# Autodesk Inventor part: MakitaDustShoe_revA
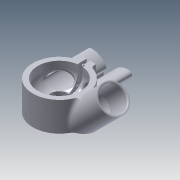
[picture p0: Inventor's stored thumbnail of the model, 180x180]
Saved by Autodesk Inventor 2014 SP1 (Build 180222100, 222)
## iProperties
Created: 2014-02
Part Number: MakitaDustShoe_revA
Material: ABS Plastic
Document SubType Name: Modeling
Designer: RagnarMac
Density: 1.06 g/cm^3
Appearance: PTFE
Author: RagnarMac
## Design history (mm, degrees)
sketch "Sketch2"
  geometry: L1 (-3.267, 9.572)-(-3.267, -36.428); L2 (-35.767, 16.355)-(-35.767, 6.355); L3 (-35.767, 16.355)-(-39.767, 16.355); L4 (-39.767, 16.355)-(-39.767, 4.355); L5 (-16.767, -13.645)-(-16.767, -17.645); L6 (-16.767, -13.645)-(-16.767, -9.969); L7 (-16.767, -9.969)-(-19.408, -13.645); L8 (-16.767, -17.645)-(-16.767, -27.645); L9 (-16.767, -27.645)-(-20.767, -27.645); L10 (-20.767, -27.645)-(-20.767, -17.094); A1 r 24.445 centre (-15.441, 6.764) between (-39.767, 4.355) and (-20.767, -17.094); A2 r 20.405 centre (-15.362, 6.355) between (-35.767, 6.355) and (-19.408, -13.645); 1 further point
  constraints: 20 end point, 4 point on circle, 3 parallel, 3 perpendicular, 2 centre point, 1 collinear, 1 point on line, 1 tangent, 1 vertical
  dimensions: "d0" = 46 distance of L1.start L1.end; "d1" = 10 distance of L2.start L2.end; "d2" = 32.5 distance between parallel lines of L1 L2; "d4" = 4 distance of L2.start L3.end; "d5" = 4 distance of L5.start L5.end; "d27" = 13.5 distance between parallel lines of L1 L5; "d42" = 20 vertical distance of L2.end L5.start; "d43" = 12 distance of L3.end L4.end; "d96" = 10 distance of L5.end L8.end; "d97" = 4 distance of L8.end L9.end
revolve "Revolution1" sketch "Sketch2" stored, may be unused: angle "d6" = 90 deg
sketch "Sketch11"
  geometry: L1 (-5.065, 36.147)-(-5.065, 46.147); L2 (-5.065, 46.147)-(-9.065, 46.147); L3 (-9.065, 46.147)-(-9.065, 35.356); L4 (-9.065, 35.356)-(-5.065, 36.147); L5 (0, 68.018)-(0, 7.693); L6 (9.065, 35.356)-(5.065, 36.147); L7 (9.065, 46.147)-(9.065, 35.356); L8 (5.065, 46.147)-(9.065, 46.147); L9 (5.065, 36.147)-(5.065, 46.147); A1 r 36.5 centre (0, 0) between (-5.065, 36.147) and (-9.065, 35.356) reference; 1 further point
  constraints: 18 end point, 4 symmetric about line, 2 perpendicular, 2 point on circle, 1 parallel, 1 vertical
  dimensions: "d28" = 10 distance of L1.start L1.end; "d29" = 4 distance of L1.end L2.end
extrude "Extrusion9" join sketch "Sketch11" distance "d30" = 10; taper "d31" = 0 deg
sketch "Sketch12"
  geometry: C1 r 1.6 at (5, 5.395); 1 further point
  constraints: 1 centre point
  dimensions: "d32" = 3.2 diameter of C1
extrude "Extrusion10" cut sketch "Sketch12" stored distance "d33" = 10; taper "d34" = 0 deg
sketch "Sketch13"
  geometry: L1 (0, 10.79)-(0, 0) reference; L2 (0, 10.79)-(-10, 10.79) reference; L3 (-10, 0)-(-10, 10.79) reference; L4 (0, 0)-(-10, 0) reference; L5 (-2.1, 3.721)-(-5, 2.047); L6 (-5, 2.047)-(-7.9, 3.721); L7 (-7.9, 3.721)-(-7.9, 7.07); L8 (-7.9, 7.07)-(-5, 8.744); L9 (-5, 8.744)-(-2.1, 7.07); L10 (-2.1, 7.07)-(-2.1, 3.721); C1 r 1.6 at (-5, 5.395) reference; 2 further points
  constraints: 12 end point, 1 coincident, 1 parallel, 13 other
  dimensions: "d35" = 5.8 distance between parallel lines of L10 L7
extrude "Extrusion11" join sketch "Sketch13" distance "d36" = 4; taper "d37" = 0 deg
sketch "Sketch15"
  geometry: L1 (-18.13, -10.79)-(-18.13, 0) reference; L2 (0, 0)-(0, -10) reference; L3 (-18.13, -8.649)-(-18.13, -14.52); L4 (-18.13, -14.52)-(-11.476, -10); L5 (-11.476, -10)-(-18.13, -8.649); 1 further point
  constraints: 6 end point, 1 parallel, 1 point on line
extrude "Extrusion12" join sketch "Sketch15" stored distance "d38" = 4; taper "d39" = 0 deg
sketch "Sketch16"
  geometry: L1 (0, 0)-(0, -10) reference; L2 (-10.13, -10)-(-5.065, -46.147); L3 (-5.065, -46.147)-(0, -10); L4 (0, -10)-(0, 0); L5 (-10.13, 0)-(0, 0); L6 (-10.13, 0)-(-10.13, -10); A1 r 36.5 centre (-5.065, -46.147) between (0, -10) and (-10.13, -10) reference; 1 further point
  constraints: 10 end point, 2 perpendicular, 1 collinear
extrude "Extrusion13" cut sketch "Sketch16" distance "d40" = 50; taper "d41" = 0 deg
fillet "Fillet5" dims "d59" = 5
fillet "Fillet6" dims "d60" = 2
sketch "Sketch17"
  geometry: L1 (-8, 0)-(-8, 10) reference; L2 (5.065, 40.511)-(5.065, -19.74); A1 r 24.445 centre (-7.109, 9.591) between (-12.435, 33.449) and (-31.435, 12) reference; 8 further points; 4 other entities
  constraints: 5 symmetric about line, 2 coincident, 2 end point, 2 vertical, 1 parallel, 8 other
extrude "Extrusion18" join sketch "Sketch17" stored distance "d62" = 10; taper "d63" = 0 deg
extrude "Extrusion19" cut sketch "Sketch17" stored distance "d64" = 33; taper "d65" = 0 deg
fillet "Fillet9" dims "d67" = 5
workplane "Work Plane4"
sketch "Sketch21"
  geometry: C1 r 17.5 at (22.26, -46.147); C2 r 20.5 at (22.26, -46.147); 4 further points; 1 other entity
  constraints: 2 centre point, 1 coincident, 1 other
  dimensions: "d76" = 35 diameter of C1; "d77" = 41 diameter of C2
extrude "Extrusion22" join sketch "Sketch21" distance "d78" = 42; taper "d79" = 0 deg
sketch "Sketch22"
  geometry: C1 r 39.904 at (13.065, -46.147); C2 r 36.5 at (13.065, -46.147); A1 r 36.5 centre (13.065, -46.147) between (-2.823, -13.286) and (23.555, -11.187) reference; A2 r 32.5 centre (13.065, -46.147) between (8.555, -13.961) and (17.575, -13.961) reference; 1 further point
  constraints: 2 centre point, 2 coincident, 1 concentric
extrude "Extrusion23" join sketch "Sketch22" distance "d80" = 44; taper "d81" = 0 deg
extrude "Extrusion24" join sketch "Sketch21" stored distance "d82" = 34; taper "d83" = 0 deg
sketch "Sketch23"
  geometry: C1 r 12.5 at (22.151, -45.865); C2 r 18 at (22.151, -45.865); 1 further point
  constraints: 2 centre point, 1 coincident
  dimensions: "d84" = 25 diameter of C1; "d85" = 36 diameter of C2
extrude "Extrusion25" join sketch "Sketch23" stored distance "d86" = 34; taper "d87" = 0 deg
extrude "Extrusion26" cut sketch "Sketch23" stored distance "d88" = 34; taper "d89" = 0 deg
fillet "Fillet10" dims "d90" = 2
fillet "Fillet11" dims "d91" = 2
fillet "Fillet12" dims "d92" = 20
chamfer "Chamfer1" distance "d93" = 5; stored, may be unused: second distance "d94" = 2, angle "d95" = 45 deg
extrude "Extrusion27" cut sketch "Sketch16" stored distance "d98" = 34; taper "d99" = 0 deg
extrude "Extrusion28" cut sketch "Sketch17" distance "d100" = 34; taper "d101" = 0 deg
sketch "Sketch24"
  geometry: L1 (0, 0)-(0, 38.982); L2 (-12.901, 11.824)-(-22.733, 28.557); L3 (-17.817, 31.856)-(-8.187, 15.467); L4 (-22.733, 28.557)-(-22.733, 31.856); L5 (-22.733, 31.856)-(-17.817, 31.856); L6 (-8.187, 15.467)-(-8.187, 11.824); L7 (-8.187, 11.824)-(-12.901, 11.824); L8 (8.187, 11.824)-(12.901, 11.824); L9 (8.187, 15.467)-(8.187, 11.824); L10 (22.733, 31.856)-(17.817, 31.856); L11 (22.733, 28.557)-(22.733, 31.856); L12 (17.817, 31.856)-(8.187, 15.467); L13 (12.901, 11.824)-(22.733, 28.557); A1 r 17.5 centre (0, 0) between (-2.428, 17.331) and (2.428, 17.331) reference; A2 r 36.5 centre (0, 0) between (-5.065, 36.147) and (-30.633, 19.846) reference; 1 further point
  constraints: 26 end point, 6 symmetric about line, 4 point on circle, 3 perpendicular, 2 parallel, 1 vertical
extrude "Extrusion29" join sketch "Sketch24" stored distance "d102" = 20; taper "d103" = 0 deg
sketch "Sketch25"
  geometry: L1 (40.316, 44)-(-34.839, 44) reference; L2 (-48.22, 77.777)-(72.822, 77.777); L3 (72.822, 77.777)-(72.822, 44); L4 (72.822, 44)-(-48.22, 44); L5 (-48.22, 44)-(-48.22, 77.777); 2 further points
  constraints: 8 end point, 2 parallel, 1 horizontal, 1 perpendicular
extrude "Extrusion30" cut sketch "Sketch25" distance "d104" = 120; taper "d105" = 0 deg
fillet "Fillet13" dims "d106" = 5
sketch "Sketch27"
  geometry: L1 (44, 19)-(34, 19) reference; L2 (44, 23)-(44, 19) reference; L3 (44, 23)-(32, 23) reference; L4 (0, 4)-(10.551, 4) reference; L5 (0, 0)-(0, 4) reference; L6 (17.676, 0)-(0, 0) reference; L7 (14, 2.641)-(17.676, 0) reference; A1 r 20.405 centre (34, -1.405) between (34, 19) and (24.312, 16.553) reference; A2 r 24.445 centre (34.409, -1.326) between (32, 23) and (10.551, 4) reference; A3 r 20.405 centre (34, -1.405) between (18.81, 12.22) and (14, 2.641) reference; 1 further point
  constraints: 1 other
extrude "Extrusion31" join sketch "Sketch27" distance "d107" = 2; taper "d108" = 0 deg
sketch "Sketch28"
  geometry: L1 (10, 0)-(10, -10) reference; L2 (10, 0)-(0, 0) reference; L3 (0, -6.566)-(0, 0) reference; L4 (-34, -6.566)-(0, -6.566) reference; L5 (-34, -10)-(-34, -6.566) reference; L6 (-2, -10)-(-34, -10) reference; L7 (10, -10)-(-2, -10) reference; L8 (3.909, -6.566)-(6.091, -6.566) reference; A1 r 1.6 centre (5, -5.395) between (6.091, -6.566) and (3.909, -6.566) reference; 2 further points
extrude "Extrusion32" join sketch "Sketch28" distance "d109" = 5; taper "d110" = 0 deg
sketch "Sketch29"
  geometry: C1 r 1.6 at (5, -5.395) reference; 1 further point
extrude "Extrusion33" cut sketch "Sketch29" stored distance "d111" = 5; taper "d112" = 0 deg
sketch "Sketch30"
  geometry: C1 r 1.6 at (5, -5.395) reference; C2 r 3 at (5, -5.395); 1 further point
  constraints: 1 centre point, 1 coincident
  dimensions: "d113" = 6 diameter of C2
extrude "Extrusion34" cut sketch "Sketch30" distance "d114" = 5; taper "d115" = 0 deg
sketch "Sketch33"
  geometry: L1 (10, 0)-(10, -7.287) reference; L2 (10, 0)-(13.028, -3.028); L3 (10, 0)-(14.282, 0); L4 (10, -7.287)-(17.287, -7.287); L5 (13.028, -3.028)-(17.287, -7.287); 1 further point
  constraints: 8 end point, 1 collinear, 1 equal length, 1 horizontal, 1 parallel
  dimensions: "d116" = 45 deg angle of L2 L3
extrude "Extrusion35" join sketch "Sketch33" stored distance "d117" = 5; taper "d118" = 0 deg
sketch "Sketch34"
  geometry: L1 (-10, 10.79)-(-10, 2.348) reference; L2 (-10, 2.348)-(-20.259, 2.348); L3 (-10, 10.79)-(-16.893, 3.897); L4 (-10, 10.79)-(-0.251, 10.79); L5 (-16.893, 3.897)-(-18.443, 2.348); 1 further point
  constraints: 8 end point, 1 collinear, 1 equal length, 1 horizontal, 1 perpendicular, 1 point on line
  dimensions: "d119" = 135 deg angle of L3 L4
extrude "Extrusion36" join sketch "Sketch34" stored distance "d120" = 5; taper "d121" = 0 deg
fillet "Fillet14" dims "d122" = 5
fillet "Fillet15" dims "d123" = 5
fillet "Fillet16" dims "d124" = 1
sketch "Sketch35"
  geometry: L1 (-2.1, 3.721)-(-5, 2.047); L2 (-5, 2.047)-(-7.9, 3.721); L3 (-7.9, 3.721)-(-7.9, 7.07); L4 (-7.9, 7.07)-(-5, 8.744); L5 (-5, 8.744)-(-2.1, 7.07); L6 (-2.1, 7.07)-(-2.1, 3.721); C1 r 1.6 at (-5, 5.395) reference; 2 further points
  constraints: 12 end point, 1 coincident, 13 other
extrude "Extrusion37" cut sketch "Sketch35" stored distance "d125" = 5; taper "d126" = 0 deg
sketch "Sketch36"
  geometry: L1 (-2.9, -1.674)-(0, 0) reference; L2 (0, 0)-(0, 3.349) reference; L3 (0, 3.349)-(-2.9, 5.023) reference; L4 (-2.9, 5.023)-(-5.8, 3.349) reference; L5 (-5.8, 3.349)-(-5.8, 0) reference; L6 (-2.9, -1.674)-(-5.8, 0) reference; C1 r 1.6 at (-2.9, 1.674) reference; 1 further point
sketch "Sketch37"
  geometry: C1 r 3 at (7.496, -9.704); 1 further point
  constraints: 1 centre point
  dimensions: "d127" = 6 diameter of C1
extrude "Extrusion38" cut sketch "Sketch37" stored distance "d128" = 10; taper "d129" = 0 deg
sketch "Sketch38"
  geometry: C1 r 3 at (7.496, -9.704); 1 further point
  constraints: 1 centre point
  dimensions: "d130" = 6 diameter of C1
extrude "Extrusion39" cut sketch "Sketch38" stored distance "d131" = 10; taper "d132" = 0 deg
fillet "Fillet17" dims "d133" = 3
sketch "Sketch39"
  geometry: 5 further points; 4 other entities
  constraints: 4 other
extrude "Extrusion40" join sketch "Sketch39" distance "d134" = 30; taper "d135" = 0 deg
sketch "Sketch40"
  geometry: L1 (-5.517, 76.147)-(-33.211, 76.147) reference; L2 (33.211, 76.147)-(5.517, 76.147) reference; L3 (0, 8.846)-(0, 81.73); L4 (-17.817, 76.147)-(-9.369, 76.147); L5 (-9.369, 76.147)-(-9.369, 35.277); L6 (-9.369, 35.277)-(-17.817, 35.277); L7 (-17.817, 35.277)-(-17.817, 76.147); L8 (9.369, 35.277)-(17.817, 35.277); L9 (17.817, 76.147)-(9.369, 76.147); L10 (9.369, 76.147)-(9.369, 35.277); L11 (17.817, 35.277)-(17.817, 76.147); A1 r 36.5 centre (0, 0) between (-5.065, 36.147) and (-17.817, 31.856) reference; 1 further point
  constraints: 18 end point, 4 symmetric about line, 2 parallel, 2 perpendicular, 1 horizontal, 1 point on circle, 1 point on line
extrude "Extrusion41" join sketch "Sketch40" distance "d136" = 14; taper "d137" = 0 deg
chamfer "Chamfer2" distance "d138" = 3; stored, may be unused: second distance "d139" = 7.25, angle "d140" = 45 deg
chamfer "Chamfer3" distance "d141" = 3; stored, may be unused: second distance "d142" = 7.25, angle "d143" = 45 deg
body "Solid1"
node "Projected Loop3"
other parameters: "d68" = 83
